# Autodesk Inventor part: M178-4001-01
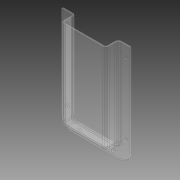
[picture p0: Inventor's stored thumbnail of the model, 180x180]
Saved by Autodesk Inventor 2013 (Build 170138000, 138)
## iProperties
Created: 2004-11
Part Number: M178-4001-01
Material: Plastic, Clear
Document SubType Name: Modeling
Designer: Autodesk, Inc.
Manufacturer: Standard
Standards Organization: Custom
Description: TOOL CADDY, PLASTIC, 2 x 3 x 1.5
Mass: 26.1813 g
Surface Area: 237.698 cm^2
Volume: 21.8178 cm^3
Density: 1.2 g/cm^3
CAGE: 1LJX3
Dept. ID: Product Design
Description #2: ---
Finish #1: ---
Finish #2: ---
Material ID: ---
Project Number: ---
Author: Autodesk, Inc.
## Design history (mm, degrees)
derived "M178-4001-XX.ipt"
body "Solid1"
tag "TaggingFeature2"
feature "Solid1::M178-4001-XX.ipt" dims "ScaleForDerivedMember" = 10
